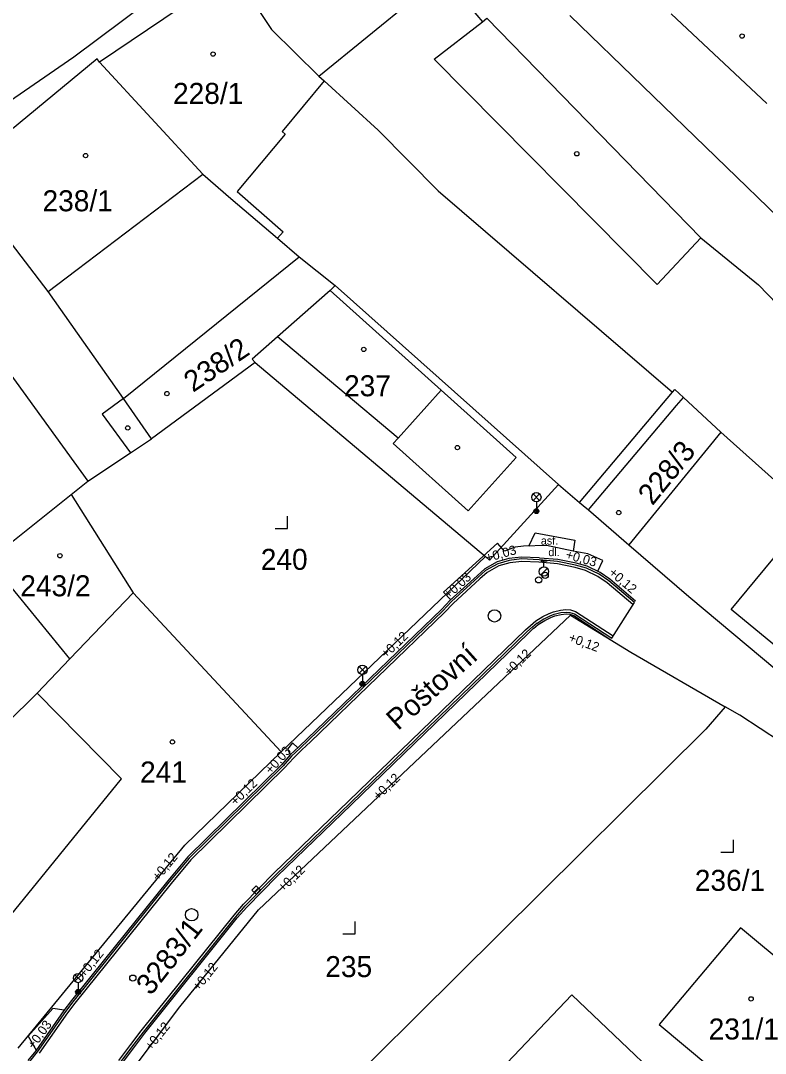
# Model space of a CAD drawing. Extents: x -600849 to -599899, y -1204328 to -1203436.
# Drawn here: x -600486.5 to -600426.3, y -1203810.6 to -1203727 of the extents above; entities that cross this region are included whole.
import ezdxf

# ---------------------------------------------------------------- set-up
doc = ezdxf.new("R2010")
doc.units = 0
for name, color, linetype in [('Vrstva 1', 7, 'Continuous'), ('Vrstva 10', 7, 'Continuous'), ('Vrstva 11', 7, 'Continuous'), ('Vrstva 2', 7, 'Continuous'), ('Vrstva 27', 7, 'Continuous'), ('Vrstva 28', 7, 'Continuous'), ('Vrstva 3', 7, 'Continuous'), ('Vrstva 33', 7, 'Continuous'), ('Vrstva 4', 7, 'Continuous'), ('Vrstva 40', 7, 'Continuous'), ('Vrstva 42', 7, 'Continuous'), ('Vrstva 5', 7, 'Continuous'), ('Vrstva 7', 7, 'Continuous')]:
    doc.layers.add(name, color=color, linetype=linetype)

msp = doc.modelspace()

# ---------------------------------------------------------------- linework, layer by layer
at = {"layer": 'Vrstva 1'}
for p, q in [((-600469.34, -1203723.1), (-600480.16, -1203730.41)), ((-600478.21, -1203757.62), (-600464, -1203746.15)), ((-600464, -1203746.15), (-600461.08, -1203748.49)), ((-600461.08, -1203748.49), (-600442.99, -1203764.57)), ((-600467.55, -1203754.71), (-600475.93, -1203760.88)), ((-600467.55, -1203754.71), (-600448.91, -1203770.42)), ((-600475.93, -1203760.88), (-600478.21, -1203757.62)), ((-600441.29, -1203766.03), (-600433.78, -1203757.11)), ((-600429.85, -1203760.36), (-600437.31, -1203769.46)), ((-600482.45, -1203765.39), (-600481.08, -1203764.32)), ((-600442.99, -1203764.57), (-600441.29, -1203766.03)), ((-600487.29, -1203769.27), (-600482.45, -1203765.39)), ((-600482.45, -1203765.39), (-600477.42, -1203773.36)), ((-600437.31, -1203769.46), (-600432.46, -1203773.64)), ((-600482.55, -1203778.7), (-600489.05, -1203770.73)), ((-600465.44, -1203786.23), (-600448.91, -1203770.42)), ((-600477.42, -1203773.36), (-600482.55, -1203778.7)), ((-600477.42, -1203773.36), (-600465.44, -1203786.23)), ((-600437.14, -1203778.16), (-600429.5, -1203782.57)), ((-600428.32, -1203783.25), (-600429.5, -1203782.57))]:
    msp.add_line(p, q, dxfattribs=at)
for points in [[(-600516.74, -1203754.05), (-600500.93, -1203742.85), (-600482.23, -1203729.97), (-600472.33, -1203722.55), (-600463.46, -1203715.87), (-600456.83, -1203710.5), (-600450.71, -1203706.1), (-600424.21, -1203680.79), (-600406.92, -1203664.19), (-600381.77, -1203639.93), (-600378.09, -1203636.25), (-600365.25, -1203624.15), (-600362.86, -1203622.3), (-600356.33, -1203617.3), (-600346.34, -1203609.78), (-600334.21, -1203600.46), (-600309.35, -1203581.63), (-600259.57, -1203537.67), (-600253.46, -1203531.77)], [(-600459.42, -1203714.97), (-600452.35, -1203723.33), (-600449.14, -1203727.13), (-600448.79, -1203726.83), (-600431.48, -1203744.63), (-600426.82, -1203748.42), (-600419.28, -1203756.23), (-600409.09, -1203765.55), (-600409.58, -1203766.13)], [(-600469.34, -1203723.1), (-600466.22, -1203727.76), (-600462.39, -1203731.53), (-600461.96, -1203731.92), (-600457.59, -1203735.9), (-600452.74, -1203740.82), (-600433.78, -1203757.11)], [(-600480.16, -1203730.41), (-600480.34, -1203730.12), (-600491.59, -1203739.41)], [(-600480.16, -1203730.41), (-600471.78, -1203739.46), (-600469.52, -1203741.43), (-600465.75, -1203744.65), (-600464, -1203746.15)], [(-600478.21, -1203757.62), (-600484.29, -1203748.96), (-600487.61, -1203744.61), (-600491.59, -1203739.41)], [(-600461.08, -1203748.49), (-600461.48, -1203748.88), (-600465.75, -1203752.64), (-600467.78, -1203754.43), (-600467.55, -1203754.71)], [(-600495.99, -1203757.53), (-600497.89, -1203754.85), (-600498.89, -1203753.29), (-600498.57, -1203753.07), (-600497.03, -1203755.41), (-600490.66, -1203751.13), (-600481.08, -1203764.32)], [(-600433.78, -1203757.11), (-600433.58, -1203756.89), (-600432.89, -1203757.53), (-600429.85, -1203760.36)], [(-600481.08, -1203764.32), (-600477.64, -1203762.03), (-600475.93, -1203760.88)], [(-600429.85, -1203760.36), (-600425, -1203764.69), (-600425.24, -1203764.95), (-600415.55, -1203773.22)], [(-600448.91, -1203770.42), (-600448.58, -1203770.7), (-600442.99, -1203764.57)], [(-600441.29, -1203766.03), (-600440.71, -1203766.53), (-600440.58, -1203766.64), (-600437.31, -1203769.46)], [(-600432.46, -1203773.64), (-600425.32, -1203779.61), (-600421.03, -1203782.13)], [(-600490.56, -1203829.3), (-600473.65, -1203806.86), (-600467.29, -1203799), (-600442.04, -1203775.17), (-600437.14, -1203778.16)], [(-600482.55, -1203778.7), (-600485.2, -1203781.47), (-600490.18, -1203786.39), (-600492.01, -1203788.21), (-600491.04, -1203789.24), (-600495.44, -1203792.84)], [(-600429.5, -1203782.57), (-600431.07, -1203784.39), (-600464.48, -1203817.52), (-600458.72, -1203823.55)], [(-600410.02, -1203797.4), (-600419.45, -1203788.97), (-600421.75, -1203787.58), (-600428.32, -1203783.25)], [(-600486.72, -1203810.21), (-600473.25, -1203793.78), (-600465.44, -1203786.23)], [(-600426.48, -1203815.28), (-600419.91, -1203807.43), (-600428.27, -1203800.45), (-600434.84, -1203808.28), (-600426.48, -1203815.28)], [(-600458.72, -1203823.55), (-600441.93, -1203805.88), (-600431.1, -1203816.2), (-600432.56, -1203817.74), (-600431.73, -1203818.53), (-600433.16, -1203820.02), (-600433.98, -1203819.23), (-600447.79, -1203833.72)]]:
    msp.add_lwpolyline(points, dxfattribs=at)
at = {"layer": 'Vrstva 10'}
for p, q in [((-600447.91, -1203770.99), (-600448.9, -1203771.54)), ((-600446.99, -1203770.73), (-600447.91, -1203770.99)), ((-600446, -1203770.61), (-600446.99, -1203770.73)), ((-600444.56, -1203770.68), (-600446, -1203770.61)), ((-600443.08, -1203770.81), (-600444.56, -1203770.68)), ((-600441.62, -1203771.1), (-600443.08, -1203770.81)), ((-600440.74, -1203771.34), (-600441.62, -1203771.1)), ((-600448.9, -1203771.54), (-600449.49, -1203772.08)), ((-600439.72, -1203771.84), (-600440.74, -1203771.34)), ((-600438.94, -1203772.37), (-600439.72, -1203771.84)), ((-600449.49, -1203772.08), (-600451.66, -1203774.06)), ((-600436.86, -1203774.14), (-600438.94, -1203772.37)), ((-600451.66, -1203774.06), (-600452.36, -1203774.8)), ((-600438.69, -1203777.01), (-600436.86, -1203774.14)), ((-600452.36, -1203774.8), (-600463.21, -1203785.26)), ((-600444.165, -1203775.454), (-600443.679, -1203775.209)), ((-600443.668, -1203775.204), (-600443.338, -1203775.068)), ((-600443.338, -1203775.068), (-600442.819, -1203774.95)), ((-600442.819, -1203774.95), (-600442.381, -1203774.91)), ((-600442.381, -1203774.91), (-600442.07, -1203774.928)), ((-600442.07, -1203774.928), (-600441.707, -1203775.037)), ((-600441.707, -1203775.037), (-600438.689, -1203777.009)), ((-600445.55, -1203776.5), (-600445.11, -1203776.11)), ((-600445.11, -1203776.11), (-600444.73, -1203775.79)), ((-600444.73, -1203775.793), (-600444.174, -1203775.459)), ((-600459.85, -1203790.37), (-600445.55, -1203776.5)), ((-600463.21, -1203785.26), (-600463.9, -1203785.92)), ((-600463.9, -1203785.92), (-600464.6, -1203786.58)), ((-600464.6, -1203786.58), (-600465.29, -1203787.36)), ((-600465.29, -1203787.36), (-600472.9, -1203794.82)), ((-600465.87, -1203796.17), (-600459.85, -1203790.37)), ((-600472.9, -1203794.82), (-600474.5, -1203796.74)), ((-600468.35, -1203798.68), (-600465.87, -1203796.17)), ((-600474.5, -1203796.74), (-600482.31, -1203806.44)), ((-600469.11, -1203799.56), (-600468.35, -1203798.68)), ((-600476.6, -1203808.91), (-600469.11, -1203799.56)), ((-600482.31, -1203806.44), (-600482.9, -1203807.23)), ((-600482.9, -1203807.23), (-600485.19, -1203810.5)), ((-600477.33, -1203809.88), (-600476.6, -1203808.91)), ((-600478.42, -1203811.31), (-600477.33, -1203809.88)), ((-600485.19, -1203810.5), (-600485.82, -1203811.29))]:
    msp.add_line(p, q, dxfattribs=at)
at = {"layer": 'Vrstva 11'}
for p, q in [((-600445.397, -1203769.568), (-600444.89, -1203768.49)), ((-600444.89, -1203768.49), (-600441.67, -1203769.1)), ((-600447.95, -1203769.34), (-600452.32, -1203773.3)), ((-600447.38, -1203769.99), (-600447.95, -1203769.34)), ((-600441.67, -1203769.1), (-600441.825, -1203769.965)), ((-600446.5, -1203769.66), (-600447.38, -1203769.99)), ((-600445.84, -1203769.58), (-600446.5, -1203769.66)), ((-600443.97, -1203769.53), (-600445.84, -1203769.58)), ((-600441.8, -1203769.97), (-600443.97, -1203769.53)), ((-600440.63, -1203770.19), (-600441.8, -1203769.97)), ((-600439.42, -1203770.72), (-600440.63, -1203770.19)), ((-600447.951, -1203770.846), (-600448.973, -1203771.409)), ((-600447.008, -1203770.581), (-600447.951, -1203770.846)), ((-600446.941, -1203770.926), (-600447.816, -1203771.172)), ((-600445.993, -1203770.46), (-600447.008, -1203770.581)), ((-600445.981, -1203770.811), (-600446.941, -1203770.926)), ((-600444.553, -1203770.53), (-600445.993, -1203770.46)), ((-600444.588, -1203770.879), (-600445.981, -1203770.811)), ((-600443.094, -1203771.011), (-600444.588, -1203770.879)), ((-600443.051, -1203770.663), (-600444.547, -1203770.531)), ((-600441.661, -1203771.296), (-600443.094, -1203771.011)), ((-600441.581, -1203770.955), (-600443.051, -1203770.663)), ((-600440.674, -1203771.205), (-600441.581, -1203770.955)), ((-600439.81, -1203771.6), (-600439.42, -1203770.72)), ((-600448.973, -1203771.409), (-600449.591, -1203771.969)), ((-600448.771, -1203771.698), (-600449.356, -1203772.228)), ((-600447.816, -1203771.172), (-600448.771, -1203771.698)), ((-600440.802, -1203771.532), (-600441.661, -1203771.296)), ((-600439.81, -1203772.021), (-600440.802, -1203771.532)), ((-600439.636, -1203771.716), (-600440.674, -1203771.205)), ((-600438.843, -1203772.256), (-600439.636, -1203771.716)), ((-600449.591, -1203771.969), (-600451.761, -1203773.949)), ((-600449.355, -1203772.228), (-600451.518, -1203774.202)), ((-600439.061, -1203772.531), (-600439.81, -1203772.021)), ((-600436.99, -1203774.293), (-600439.061, -1203772.531)), ((-600436.763, -1203774.026), (-600438.843, -1203772.256)), ((-600452.32, -1203773.3), (-600451.724, -1203773.915)), ((-600451.761, -1203773.949), (-600452.469, -1203774.697)), ((-600451.518, -1203774.202), (-600452.215, -1203774.938)), ((-600452.464, -1203774.692), (-600463.314, -1203785.152)), ((-600452.221, -1203774.944), (-600463.071, -1203785.404)), ((-600444.833, -1203775.622), (-600444.257, -1203775.276)), ((-600444.257, -1203775.276), (-600443.768, -1203775.03)), ((-600443.768, -1203775.03), (-600443.396, -1203774.876)), ((-600443.611, -1203775.343), (-600443.289, -1203775.21)), ((-600443.396, -1203774.876), (-600442.843, -1203774.751)), ((-600443.289, -1203775.21), (-600442.795, -1203775.098)), ((-600442.843, -1203774.751), (-600442.394, -1203774.709)), ((-600442.795, -1203775.098), (-600442.383, -1203775.06)), ((-600442.394, -1203774.709), (-600442.033, -1203774.73)), ((-600442.383, -1203775.06), (-600442.096, -1203775.077)), ((-600442.096, -1203775.077), (-600441.771, -1203775.175)), ((-600442.033, -1203774.73), (-600441.622, -1203774.855)), ((-600441.771, -1203775.175), (-600438.752, -1203777.147)), ((-600441.622, -1203774.855), (-600438.582, -1203776.84)), ((-600445.681, -1203776.348), (-600445.27, -1203775.984)), ((-600445.27, -1203775.984), (-600444.827, -1203775.611)), ((-600445.013, -1203776.225), (-600444.653, -1203775.922)), ((-600444.653, -1203775.922), (-600444.097, -1203775.588)), ((-600444.097, -1203775.588), (-600443.611, -1203775.343)), ((-600459.984, -1203790.222), (-600445.681, -1203776.348)), ((-600459.746, -1203790.478), (-600445.441, -1203776.603)), ((-600445.441, -1203776.603), (-600445.011, -1203776.222)), ((-600463.314, -1203785.152), (-600464.004, -1203785.812)), ((-600464.52, -1203785.49), (-600464.93, -1203785.99)), ((-600464.93, -1203785.99), (-600464.681, -1203786.45)), ((-600464.003, -1203785.811), (-600464.704, -1203786.472)), ((-600464.084, -1203785.888), (-600464.52, -1203785.49)), ((-600463.766, -1203786.069), (-600464.454, -1203786.718)), ((-600463.072, -1203785.405), (-600463.766, -1203786.069)), ((-600464.704, -1203786.472), (-600465.394, -1203787.252)), ((-600464.454, -1203786.718), (-600465.141, -1203787.494)), ((-600465.394, -1203787.252), (-600473.01, -1203794.717)), ((-600465.141, -1203787.494), (-600472.752, -1203794.955)), ((-600466.008, -1203796.024), (-600459.984, -1203790.222)), ((-600465.763, -1203796.275), (-600459.746, -1203790.478)), ((-600473.01, -1203794.717), (-600474.627, -1203796.658)), ((-600472.752, -1203794.955), (-600474.349, -1203796.871)), ((-600468.495, -1203798.543), (-600466.008, -1203796.024)), ((-600474.627, -1203796.658), (-600482.427, -1203806.346)), ((-600474.349, -1203796.871), (-600482.154, -1203806.565)), ((-600468.236, -1203798.778), (-600465.763, -1203796.275)), ((-600469.258, -1203799.425), (-600468.495, -1203798.543)), ((-600476.769, -1203808.801), (-600469.258, -1203799.425)), ((-600468.993, -1203799.654), (-600468.236, -1203798.778)), ((-600476.48, -1203809), (-600468.993, -1203799.654)), ((-600483.92, -1203807), (-600485.91, -1203809.23)), ((-600483.01, -1203807.13), (-600483.92, -1203807)), ((-600482.427, -1203806.346), (-600483.023, -1203807.144)), ((-600482.15, -1203806.56), (-600482.74, -1203807.35)), ((-600483.023, -1203807.144), (-600485.31, -1203810.41)), ((-600482.736, -1203807.345), (-600485.026, -1203810.615)), ((-600485.91, -1203809.23), (-600485.28, -1203810.36)), ((-600477.601, -1203809.906), (-600476.769, -1203808.801)), ((-600477.211, -1203809.971), (-600476.48, -1203809)), ((-600478.58, -1203811.192), (-600477.601, -1203809.906)), ((-600478.298, -1203811.398), (-600477.211, -1203809.971)), ((-600485.31, -1203810.41), (-600485.937, -1203811.197))]:
    msp.add_line(p, q, dxfattribs=at)
at = {"layer": 'Vrstva 27'}
msp.add_line((-600467.634, -1203797.588), (-600467.29, -1203797.225), dxfattribs=at)
msp.add_lwpolyline([(-600467.453, -1203797.76), (-600467.109, -1203797.398), (-600467.471, -1203797.053), (-600467.815, -1203797.415)], close=True, dxfattribs=at)
for centre in [(-600448.18, -1203775.22), (-600472.69, -1203799.4)]:
    msp.add_circle(centre, 0.5, dxfattribs=at)
at = {"layer": 'Vrstva 28'}
for p, q in [((-600444.43, -1203770.755), (-600443.93, -1203770.755)), ((-600444.18, -1203771.255), (-600444.18, -1203770.755)), ((-600444.438, -1203771.902), (-600443.908, -1203771.372))]:
    msp.add_line(p, q, dxfattribs=at)
for centre, radius in [((-600444.18, -1203771.63), 0.375), ((-600444.08, -1203771.93), 0.25), ((-600444.6, -1203772.3), 0.25), ((-600477.45, -1203804.53), 0.25)]:
    msp.add_circle(centre, radius, dxfattribs=at)
at = {"layer": 'Vrstva 3'}
for p, q in [((-600464.94, -1203768.15), (-600464.94, -1203767.15)), ((-600465.941, -1203768.15), (-600464.94, -1203768.15)), ((-600428.85, -1203794.34), (-600428.85, -1203793.34)), ((-600429.851, -1203794.34), (-600428.85, -1203794.34)), ((-600459.45, -1203800.95), (-600459.45, -1203799.95)), ((-600460.451, -1203800.95), (-600459.45, -1203800.95))]:
    msp.add_line(p, q, dxfattribs=at)
at = {"layer": 'Vrstva 33'}
for p, q in [((-600445.055, -1203765.88), (-600444.525, -1203765.35)), ((-600445.055, -1203765.35), (-600444.525, -1203765.88)), ((-600444.79, -1203765.99), (-600444.79, -1203766.74)), ((-600459.135, -1203779.85), (-600458.605, -1203779.32)), ((-600459.135, -1203779.32), (-600458.605, -1203779.85)), ((-600458.87, -1203779.96), (-600458.87, -1203780.71)), ((-600482.145, -1203804.79), (-600481.615, -1203804.26)), ((-600482.145, -1203804.26), (-600481.615, -1203804.79)), ((-600481.88, -1203804.9), (-600481.88, -1203805.65))]:
    msp.add_line(p, q, dxfattribs=at)
for centre, radius in [((-600444.79, -1203765.615), 0.375), ((-600444.79, -1203766.74), 0.2), ((-600444.79, -1203766.74), 0.145), ((-600444.79, -1203766.74), 0.0876), ((-600458.87, -1203779.585), 0.375), ((-600458.87, -1203780.71), 0.2), ((-600458.87, -1203780.71), 0.145), ((-600458.87, -1203780.71), 0.0876), ((-600481.88, -1203804.525), 0.375), ((-600481.88, -1203805.65), 0.2), ((-600481.88, -1203805.65), 0.145), ((-600481.88, -1203805.65), 0.0876)]:
    msp.add_circle(centre, radius, dxfattribs=at)
at = {"layer": 'Vrstva 4'}
for p, q in [((-600462.39, -1203731.53), (-600452.35, -1203723.33)), ((-600442.07, -1203726.63), (-600422.71, -1203745.4)), ((-600426.13, -1203733.75), (-600433.89, -1203726.48)), ((-600453.06, -1203730.17), (-600449.14, -1203727.13)), ((-600435.02, -1203748.39), (-600453.06, -1203730.17)), ((-600461.96, -1203731.92), (-600465.37, -1203736)), ((-600465.37, -1203736), (-600465.12, -1203736.22)), ((-600465.12, -1203736.22), (-600469, -1203740.86)), ((-600484.29, -1203748.96), (-600471.78, -1203739.46)), ((-600469, -1203740.86), (-600465.27, -1203744.13)), ((-600465.27, -1203744.13), (-600465.75, -1203744.65)), ((-600431.48, -1203744.63), (-600435.02, -1203748.39)), ((-600461.48, -1203748.88), (-600452.5, -1203756.96)), ((-600455.97, -1203760.82), (-600465.75, -1203752.64)), ((-600478.21, -1203757.62), (-600479.94, -1203758.89)), ((-600455.97, -1203760.82), (-600452.5, -1203756.96)), ((-600452.5, -1203756.96), (-600446.43, -1203762.41)), ((-600433.44, -1203758.18), (-600432.89, -1203757.53)), ((-600440.58, -1203766.64), (-600433.44, -1203758.18)), ((-600479.94, -1203758.89), (-600477.64, -1203762.03)), ((-600456.37, -1203761.27), (-600455.97, -1203760.82)), ((-600450.31, -1203766.72), (-600456.37, -1203761.27)), ((-600446.43, -1203762.41), (-600450.31, -1203766.72)), ((-600429.02, -1203774.7), (-600423.05, -1203767.46)), ((-600425.2, -1203777.85), (-600429.02, -1203774.7)), ((-600478.38, -1203788.41), (-600485.2, -1203781.47)), ((-600489.46, -1203802.03), (-600478.38, -1203788.41))]:
    msp.add_line(p, q, dxfattribs=at)
at = {"layer": 'Vrstva 5'}
for centre in [(-600428.137, -1203728.289), (-600470.957, -1203729.749), (-600441.517, -1203737.819), (-600481.277, -1203737.959), (-600458.767, -1203753.649), (-600474.697, -1203757.229), (-600477.857, -1203759.999), (-600451.177, -1203761.599), (-600438.127, -1203766.859), (-600483.357, -1203770.349), (-600474.247, -1203785.419), (-600427.417, -1203806.209)]:
    msp.add_circle(centre, 0.175, dxfattribs=at)

# ---------------------------------------------------------------- texts
at = {"layer": 'Vrstva 2'}
for s, p in [('228/1', (-600474.198, -1203733.78)), ('238/1', (-600484.758, -1203742.47)), ('237', (-600460.355, -1203757.44)), ('240', (-600467.095, -1203771.49)), ('243/2', (-600486.558, -1203773.63)), ('241', (-600476.865, -1203788.7)), ('236/1', (-600431.968, -1203797.47)), ('235', (-600461.875, -1203804.45)), ('231/1', (-600430.848, -1203809.5))]:
    msp.add_text(s, height=1.7, dxfattribs=at).set_placement(p)
for s, rotation, p in [('238/2', 34, (-600472.579, -1203757.169)), ('228/3', 51, (-600435.395, -1203766.348)), ('3283/1', 52, (-600475.99, -1203806.014))]:
    msp.add_text(s, height=1.7, rotation=rotation, dxfattribs=at).set_placement(p)
at = {"layer": 'Vrstva 40'}
for s, p in [('asf.', (-600444.427, -1203769.451)), ('dl.', (-600443.822, -1203770.382))]:
    msp.add_text(s, height=0.65, dxfattribs=at).set_placement(p)
at = {"layer": 'Vrstva 42'}
for s, rotation, p in [('+0,03', 15.78075, (-600448.791, -1203770.887)), ('+0,03', 344.58999, (-600442.478, -1203770.573)), ('+0,03', 42.37865, (-600451.872, -1203773.886)), ('+0,12', 319.60349, (-600438.994, -1203771.817)), ('+0,12', 43.95153, (-600456.939, -1203778.701)), ('+0,12', 339.59012, (-600442.248, -1203777.257)), ('+0,12', 44.12579, (-600446.985, -1203780.12)), ('+0,03', 48.50353, (-600466.273, -1203788.077)), ('+0,12', 44.42634, (-600469.127, -1203790.623)), ('+0,12', 44.12548, (-600457.574, -1203790.182)), ('+0,12', 50.19443, (-600475.397, -1203796.722)), ('+0,12', 43.93371, (-600465.28, -1203797.614)), ('+0,12', 51.16177, (-600481.351, -1203804.55)), ('+0,12', 51.30285, (-600472.111, -1203805.626)), ('+0,03', 54.28839, (-600485.449, -1203810.353)), ('+0,12', 51.30285, (-600475.971, -1203810.444))]:
    msp.add_text(s, height=0.75, rotation=rotation, dxfattribs=at).set_placement(p)
at = {"layer": 'Vrstva 7'}
msp.add_text('Poštovní', height=1.7, rotation=42, dxfattribs=at).set_placement((-600455.984, -1203784.554))

doc.saveas('drawing.dxf')
